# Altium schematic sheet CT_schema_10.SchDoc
size 318 x 188 mm
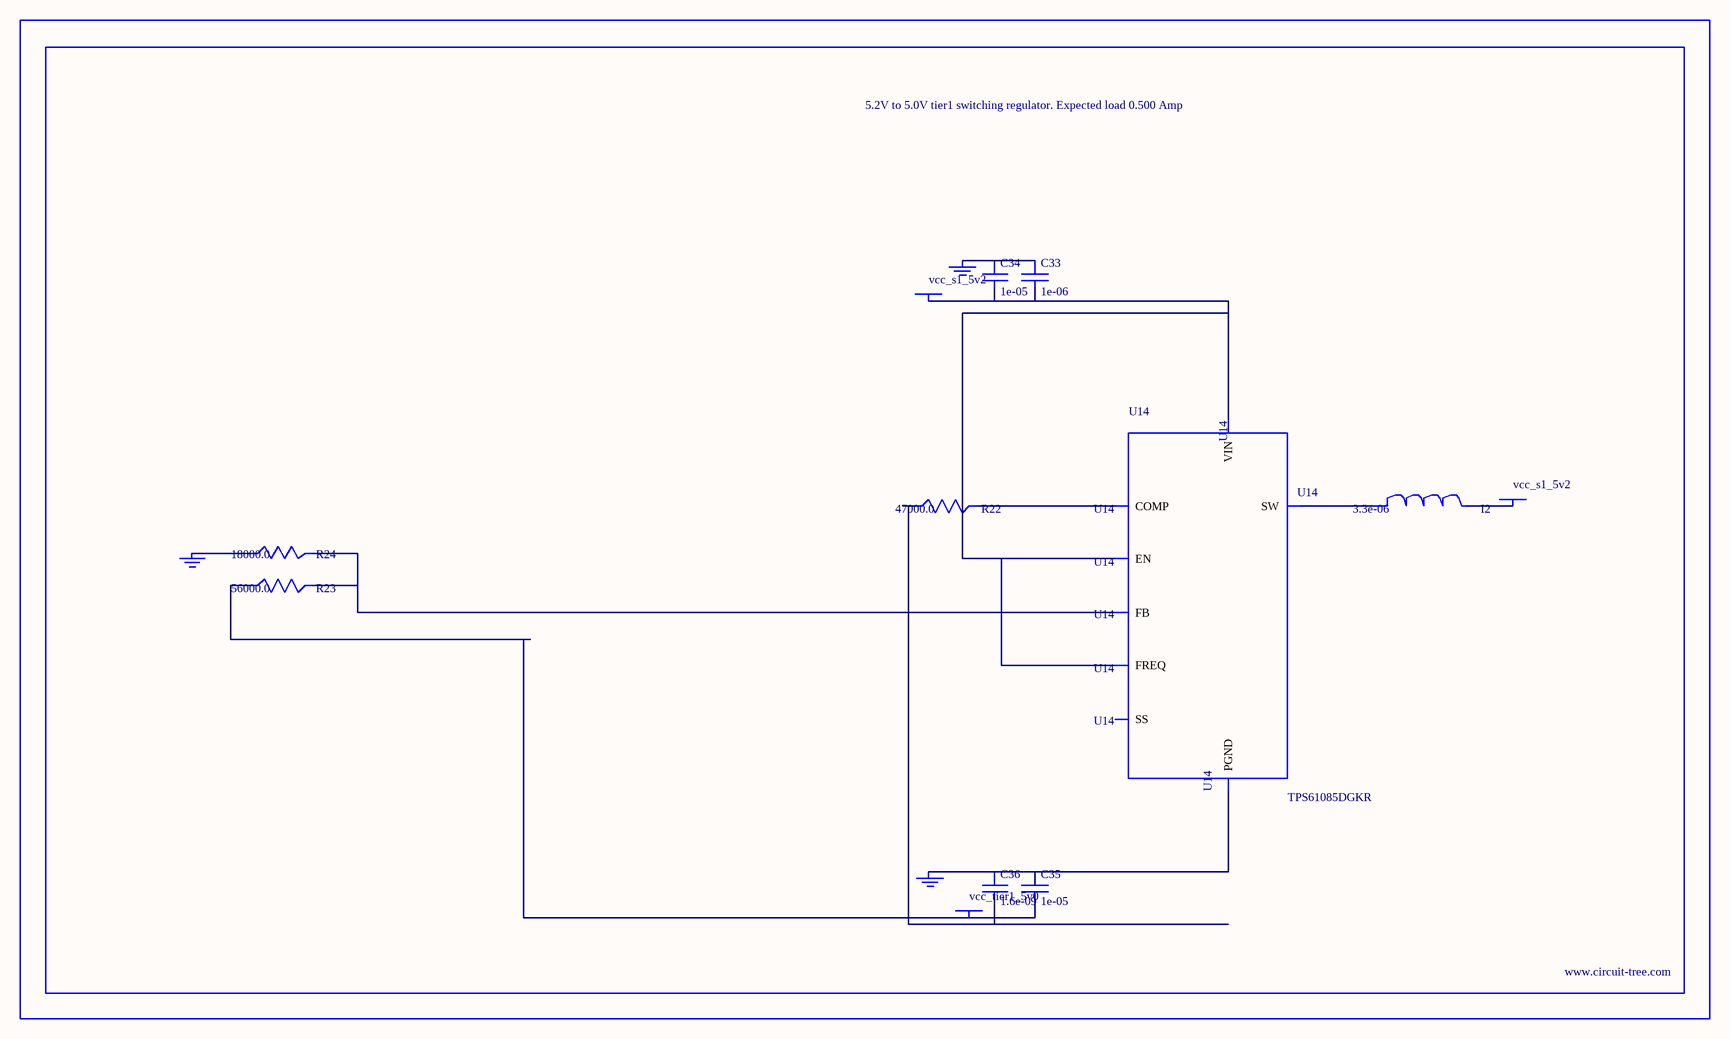
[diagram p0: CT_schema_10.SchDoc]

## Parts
BORDER9  (no value)
C33  1e-06  [C0603]
C34  1e-05  [C0805]
C35  1e-05  [C0805]
C36  1.6e-09  [C0603]
GND_INSTANCE_9_0  (no value)
GND_INSTANCE_9_1  (no value)
GND_INSTANCE_9_2  (no value)
I2  3.3e-06  [L0806]
POWER_INSTANCE_9_0  vcc_tier1_5v0
POWER_INSTANCE_9_1  vcc_s1_5v2
POWER_INSTANCE_9_2  vcc_s1_5v2
R22  47000.0  [R0603]
R23  56000.0  [R0603]
R24  18000.0  [R0603]
U14  TPS61085DGKR  [MSOP-8]

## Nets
NetC33_1: C33.1 C34.1 GND_INSTANCE_9_2.0(GND)
NetC33_2: C33.2 C34.2 POWER_INSTANCE_9_2.0(PWR) U14.3(EN) U14.6(VIN) U14.7(FREQ)
NetC35_1: C35.1 C36.1 GND_INSTANCE_9_1.0(GND) U14.4(PGND)
NetC35_2: C35.2 POWER_INSTANCE_9_0.0(PWR) R23.1
NetC36_2: C36.2 R22.1
NetGND_INSTANCE_9_0_0: GND_INSTANCE_9_0.0(GND) R24.1
NetI2_1: I2.1 U14.5(SW)
NetI2_2: I2.2 POWER_INSTANCE_9_1.0(PWR)
NetR22_2: R22.2 U14.1(COMP)
NetR23_2: R23.2 R24.2 U14.2(FB)

Not connected (* = marked no-connect by the designer): U14 8(SS)

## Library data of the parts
BORDER9 = BORDER_PAGE9
C33 = C0603C105K3RACTU
C34 C35 = C0805C106K8RACTU
C36 = 06035C162JAT2A
GND_INSTANCE_9_0-GND_INSTANCE_9_2 = GND
I2 = L0806C3R3MDWIT
POWER_INSTANCE_9_0-POWER_INSTANCE_9_2 = PWR
R22 = RC0603JR-0747KL
R23 = RC0603JR-0756KL
R24 = RC0603JR-0718KL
